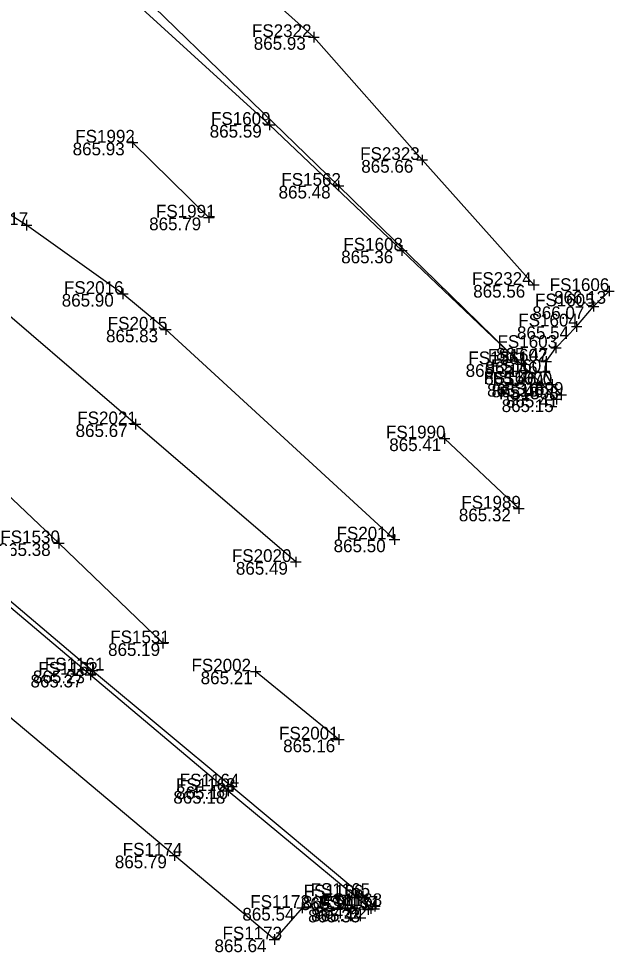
# Model space of a CAD drawing. Extents: x 1479420 to 1479833, y 379731 to 380103.
# Drawn here: x 1479768.1 to 1479824.3, y 379731.9 to 379820.1 of the extents above; entities that cross this region are included whole.
import ezdxf

# ---------------------------------------------------------------- set-up
doc = ezdxf.new("R2010")
doc.units = 0
for name, color, linetype in [('PM_X_CL_Double_Solid', 7, 'Continuous'), ('PM_X_Lane_Line', 7, 'Continuous'), ('PV_X_Curb', 7, 'Continuous'), ('PV_X_Walk', 7, 'Continuous'), ('SV_X_Shot_Marker', 7, 'Continuous'), ('SV_X_Text_Elevation', 7, 'Continuous'), ('SV_X_Text_Name', 7, 'Continuous'), ('UT_X_Gas', 7, 'Continuous'), ('UT_X_Water', 7, 'Continuous')]:
    doc.layers.add(name, color=color, linetype=linetype)

msp = doc.modelspace()

# ---------------------------------------------------------------- linework, layer by layer
at = {"layer": 'PM_X_CL_Double_Solid'}
for points in [[(1479794.219, 379768.772), (1479779.093, 379781.771), (1479763.159, 379795.427), (1479746.619, 379810.624), (1479732.239, 379823.873), (1479714.719, 379840.653), (1479700.713, 379853.615), (1479677.934, 379875.066)], [(1479803.529, 379770.896), (1479781.948, 379790.708), (1479777.891, 379794.074), (1479768.812, 379800.571), (1479752.353, 379810.888), (1479732.762, 379823.628)]]:
    msp.add_lwpolyline(points, dxfattribs=at)
at = {"layer": 'PM_X_Lane_Line'}
for p, q in [((1479786.008, 379801.285), (1479778.818, 379808.36)), ((1479815.248, 379773.81), (1479808.249, 379780.438)), ((1479798.265, 379752.014), (1479790.425, 379758.434))]:
    msp.add_line(p, q, dxfattribs=at)
at = {"layer": 'PV_X_Curb'}
for points in [[(1479818.811, 379784.125), (1479817.439, 379785.583), (1479804.233, 379798.167), (1479791.741, 379810.033), (1479778.638, 379821.983), (1479775.464, 379824.819), (1479758.378, 379840.845), (1479740.8, 379857.042), (1479740.592, 379857.626), (1479737.808, 379860.038), (1479735.87, 379861.852), (1479733.787, 379863.763), (1479718.701, 379877.898), (1479705.478, 379890.334), (1479700.95, 379894.575), (1479699.048, 379897.264), (1479697.778, 379899.5), (1479696.445, 379902.732), (1479695.776, 379905.397), (1479695.475, 379907.419), (1479695.142, 379911.53), (1479695.083, 379915.321)], [(1479667.239, 379857.122), (1479681.024, 379844.208), (1479695.135, 379830.978), (1479709.331, 379817.708), (1479723.729, 379804.193), (1479729.719, 379798.6), (1479748.963, 379780.548), (1479759.065, 379771.485), (1479760.185, 379770.473), (1479774.837, 379758.13), (1479787.835, 379747.16), (1479799.962, 379737.109), (1479801.3, 379736.045)], [(1479667.529, 379857.521), (1479681.356, 379844.557), (1479695.384, 379831.416), (1479709.512, 379818.131), (1479724.003, 379804.728), (1479730.662, 379798.272), (1479750.68, 379779.69), (1479759.253, 379771.893), (1479760.555, 379770.78), (1479775.03, 379758.526), (1479788.183, 379747.585), (1479800.537, 379737.251), (1479801.677, 379736.292)], [(1479819.259, 379784.557), (1479818.41, 379785.516), (1479817.726, 379786.711), (1479817.841, 379787.691), (1479818.764, 379788.982), (1479820.716, 379791.008), (1479822.306, 379792.903), (1479823.77, 379794.351)]]:
    msp.add_lwpolyline(points, dxfattribs=at)
at = {"layer": 'PV_X_Walk'}
msp.add_lwpolyline([(1479801.031, 379735.954), (1479794.804, 379736.123), (1479792.191, 379733.142), (1479782.769, 379741.06), (1479767.055, 379754.294), (1479759.061, 379761.026), (1479757.309, 379762.481), (1479754.256, 379765.105), (1479744.261, 379773.561), (1479732.859, 379783.688), (1479719.35, 379796.384), (1479703.027, 379811.462), (1479682.443, 379830.686), (1479657.296, 379854.468)], dxfattribs=at)
at = {"layer": 'SV_X_Shot_Marker'}
for p, q in [((1479795.406, 379818.324), (1479796.406, 379818.324)), ((1479795.906, 379818.824), (1479795.906, 379817.824)), ((1479795.906, 379818.324), (1479795.906, 379818.324)), ((1479791.741, 379810.533), (1479791.741, 379809.533)), ((1479791.241, 379810.033), (1479792.241, 379810.033)), ((1479791.741, 379810.033), (1479791.741, 379810.033)), ((1479778.818, 379808.86), (1479778.818, 379807.86)), ((1479778.318, 379808.36), (1479779.318, 379808.36)), ((1479778.818, 379808.36), (1479778.818, 379808.36)), ((1479805.628, 379806.719), (1479806.628, 379806.719)), ((1479806.128, 379807.219), (1479806.128, 379806.219)), ((1479806.128, 379806.719), (1479806.128, 379806.719)), ((1479797.748, 379804.283), (1479798.748, 379804.283)), ((1479798.248, 379804.783), (1479798.248, 379803.783)), ((1479798.248, 379804.283), (1479798.248, 379804.283)), ((1479786.008, 379801.785), (1479786.008, 379800.785)), ((1479768.312, 379800.571), (1479769.312, 379800.571)), ((1479768.812, 379801.071), (1479768.812, 379800.071)), ((1479768.812, 379800.571), (1479768.812, 379800.571)), ((1479785.508, 379801.285), (1479786.508, 379801.285)), ((1479786.008, 379801.285), (1479786.008, 379801.285)), ((1479803.733, 379798.167), (1479804.733, 379798.167)), ((1479804.233, 379798.667), (1479804.233, 379797.667)), ((1479804.233, 379798.167), (1479804.233, 379798.167)), ((1479816.671, 379795.427), (1479816.671, 379794.427)), ((1479777.891, 379794.574), (1479777.891, 379793.574)), ((1479816.171, 379794.927), (1479817.171, 379794.927)), ((1479816.671, 379794.927), (1479816.671, 379794.927)), ((1479823.27, 379794.351), (1479824.27, 379794.351)), ((1479823.77, 379794.851), (1479823.77, 379793.851)), ((1479823.77, 379794.351), (1479823.77, 379794.351)), ((1479777.391, 379794.074), (1479778.391, 379794.074)), ((1479777.891, 379794.074), (1479777.891, 379794.074)), ((1479821.806, 379792.903), (1479822.806, 379792.903)), ((1479822.306, 379793.403), (1479822.306, 379792.403)), ((1479822.306, 379792.903), (1479822.306, 379792.903)), ((1479781.948, 379791.208), (1479781.948, 379790.208)), ((1479820.216, 379791.008), (1479821.216, 379791.008)), ((1479820.716, 379791.508), (1479820.716, 379790.508)), ((1479820.716, 379791.008), (1479820.716, 379791.008)), ((1479781.448, 379790.708), (1479782.448, 379790.708)), ((1479781.948, 379790.708), (1479781.948, 379790.708)), ((1479818.764, 379789.482), (1479818.764, 379788.482)), ((1479817.841, 379788.191), (1479817.841, 379787.191)), ((1479818.264, 379788.982), (1479819.264, 379788.982)), ((1479818.764, 379788.982), (1479818.764, 379788.982)), ((1479814.968, 379787.444), (1479815.968, 379787.444)), ((1479815.468, 379787.944), (1479815.468, 379786.944)), ((1479815.468, 379787.444), (1479815.468, 379787.444)), ((1479817.341, 379787.691), (1479818.341, 379787.691)), ((1479817.841, 379787.691), (1479817.841, 379787.691)), ((1479817.226, 379786.711), (1479818.226, 379786.711)), ((1479817.726, 379787.211), (1479817.726, 379786.211)), ((1479817.726, 379786.711), (1479817.726, 379786.711)), ((1479816.939, 379785.583), (1479817.939, 379785.583)), ((1479817.439, 379786.083), (1479817.439, 379785.083)), ((1479817.439, 379785.583), (1479817.439, 379785.583)), ((1479817.91, 379785.516), (1479818.91, 379785.516)), ((1479818.41, 379786.016), (1479818.41, 379785.016)), ((1479818.41, 379785.516), (1479818.41, 379785.516)), ((1479818.811, 379784.625), (1479818.811, 379783.625)), ((1479819.259, 379785.057), (1479819.259, 379784.057)), ((1479818.311, 379784.125), (1479819.311, 379784.125)), ((1479818.759, 379784.557), (1479819.759, 379784.557)), ((1479818.811, 379784.125), (1479818.811, 379784.125)), ((1479819.259, 379784.557), (1479819.259, 379784.557)), ((1479779.093, 379782.271), (1479779.093, 379781.271)), ((1479778.593, 379781.771), (1479779.593, 379781.771)), ((1479779.093, 379781.771), (1479779.093, 379781.771)), ((1479807.749, 379780.438), (1479808.749, 379780.438)), ((1479808.249, 379780.938), (1479808.249, 379779.938)), ((1479808.249, 379780.438), (1479808.249, 379780.438)), ((1479815.248, 379774.31), (1479815.248, 379773.31)), ((1479814.748, 379773.81), (1479815.748, 379773.81)), ((1479815.248, 379773.81), (1479815.248, 379773.81)), ((1479803.529, 379771.396), (1479803.529, 379770.396)), ((1479771.342, 379770.542), (1479772.342, 379770.542)), ((1479771.842, 379771.042), (1479771.842, 379770.042)), ((1479771.842, 379770.542), (1479771.842, 379770.542)), ((1479803.029, 379770.896), (1479804.029, 379770.896)), ((1479803.529, 379770.896), (1479803.529, 379770.896)), ((1479793.719, 379768.772), (1479794.719, 379768.772)), ((1479794.219, 379769.272), (1479794.219, 379768.272)), ((1479794.219, 379768.772), (1479794.219, 379768.772)), ((1479781.178, 379761.101), (1479782.178, 379761.101)), ((1479781.678, 379761.601), (1479781.678, 379760.601)), ((1479781.678, 379761.101), (1479781.678, 379761.101)), ((1479774.53, 379758.526), (1479775.53, 379758.526)), ((1479774.837, 379758.63), (1479774.837, 379757.63)), ((1479775.03, 379759.026), (1479775.03, 379758.026)), ((1479775.03, 379758.526), (1479775.03, 379758.526)), ((1479789.925, 379758.434), (1479790.925, 379758.434)), ((1479790.425, 379758.934), (1479790.425, 379757.934)), ((1479790.425, 379758.434), (1479790.425, 379758.434)), ((1479774.337, 379758.13), (1479775.337, 379758.13)), ((1479774.837, 379758.13), (1479774.837, 379758.13)), ((1479797.765, 379752.014), (1479798.765, 379752.014)), ((1479798.265, 379752.514), (1479798.265, 379751.514)), ((1479798.265, 379752.014), (1479798.265, 379752.014)), ((1479787.683, 379747.585), (1479788.683, 379747.585)), ((1479787.835, 379747.66), (1479787.835, 379746.66)), ((1479788.183, 379748.085), (1479788.183, 379747.085)), ((1479788.183, 379747.585), (1479788.183, 379747.585)), ((1479787.335, 379747.16), (1479788.335, 379747.16)), ((1479787.835, 379747.16), (1479787.835, 379747.16)), ((1479782.769, 379741.56), (1479782.769, 379740.56)), ((1479782.269, 379741.06), (1479783.269, 379741.06)), ((1479782.769, 379741.06), (1479782.769, 379741.06)), ((1479799.462, 379737.109), (1479800.462, 379737.109)), ((1479799.962, 379737.609), (1479799.962, 379736.609)), ((1479799.962, 379737.109), (1479799.962, 379737.109)), ((1479800.037, 379737.251), (1479801.037, 379737.251)), ((1479800.537, 379737.751), (1479800.537, 379736.751)), ((1479800.537, 379737.251), (1479800.537, 379737.251)), ((1479794.804, 379736.623), (1479794.804, 379735.623)), ((1479801.031, 379736.454), (1479801.031, 379735.454)), ((1479801.177, 379736.292), (1479802.177, 379736.292)), ((1479801.3, 379736.545), (1479801.3, 379735.545)), ((1479801.677, 379736.792), (1479801.677, 379735.792)), ((1479801.677, 379736.292), (1479801.677, 379736.292)), ((1479794.304, 379736.123), (1479795.304, 379736.123)), ((1479794.804, 379736.123), (1479794.804, 379736.123)), ((1479800.531, 379735.954), (1479801.531, 379735.954)), ((1479800.8, 379736.045), (1479801.8, 379736.045)), ((1479801.031, 379735.954), (1479801.031, 379735.954)), ((1479801.3, 379736.045), (1479801.3, 379736.045)), ((1479792.191, 379733.642), (1479792.191, 379732.642)), ((1479791.691, 379733.142), (1479792.691, 379733.142)), ((1479792.191, 379733.142), (1479792.191, 379733.142))]:
    msp.add_line(p, q, dxfattribs=at)
at = {"layer": 'UT_X_Gas'}
msp.add_lwpolyline([(1479667.444, 379946.572), (1479666.862, 379942.802), (1479667.538, 379940.507), (1479675.403, 379934.504), (1479682.743, 379926.326), (1479692.421, 379916.824), (1479702.659, 379906.694), (1479713.881, 379895.567), (1479724.225, 379885.781), (1479733.117, 379877.795), (1479742.697, 379869.326), (1479754.816, 379857.131), (1479762.869, 379849.318), (1479772.436, 379840.641), (1479780.346, 379832.715), (1479784.901, 379828.191), (1479795.906, 379818.324), (1479806.128, 379806.719), (1479816.671, 379794.927)], dxfattribs=at)
at = {"layer": 'UT_X_Water'}
for points in [[(1479473.217, 380054.881), (1479498.741, 380029.974), (1479514.505, 380014.086), (1479533.448, 379996.735), (1479556.003, 379974.319), (1479574.861, 379956.271), (1479584.403, 379947.432), (1479599.597, 379932.819), (1479630.106, 379903.783), (1479644.769, 379889.722), (1479654.209, 379882.356), (1479664.266, 379872.629), (1479692.509, 379845.847), (1479712.672, 379826.686), (1479730.739, 379809.85), (1479753.15, 379788.309), (1479771.842, 379770.542), (1479781.678, 379761.101)], [(1479682.752, 379913.809), (1479688.353, 379908.314), (1479695.924, 379900.161), (1479705.441, 379891.596), (1479719.261, 379878.171), (1479726.79, 379870.913), (1479729.608, 379870.544), (1479735.551, 379869.684), (1479739.947, 379866.49), (1479744.65, 379861.847), (1479745.833, 379856.023), (1479753.929, 379847.124), (1479764.701, 379835.97), (1479779.815, 379822.167), (1479798.248, 379804.283), (1479815.468, 379787.444)]]:
    msp.add_lwpolyline(points, dxfattribs=at)

# ---------------------------------------------------------------- texts
at = {"layer": 'SV_X_Text_Elevation'}
for s, p in [('865.93', (1479790.247, 379817.124)), ('865.59', (1479786.091, 379808.833)), ('865.93', (1479773.159, 379807.16)), ('865.66', (1479800.393, 379805.519)), ('865.48', (1479792.589, 379803.083)), ('865.79', (1479780.377, 379800.085)), ('865.36', (1479798.498, 379796.967)), ('865.56', (1479810.955, 379793.727)), ('866.13', (1479818.584, 379793.151)), ('865.90', (1479772.128, 379792.874)), ('866.07', (1479816.533, 379791.703)), ('865.54', (1479815.085, 379789.808)), ('865.83', (1479776.307, 379789.508)), ('865.47', (1479813.114, 379787.782)), ('865.31', (1479810.242, 379786.244)), ('865.46', (1479812.116, 379786.491)), ('865.46', (1479812.001, 379785.511)), ('865.19', (1479812.262, 379784.383)), ('865.46', (1479812.685, 379784.316)), ('865.15', (1479813.643, 379782.925)), ('865.41', (1479814.043, 379783.357)), ('865.67', (1479773.434, 379780.571)), ('865.41', (1479803.033, 379779.238)), ('865.32', (1479809.598, 379772.61)), ('865.38', (1479766.173, 379769.342)), ('865.50', (1479797.784, 379769.696)), ('865.49', (1479788.56, 379767.572)), ('865.19', (1479776.501, 379759.901)), ('865.23', (1479769.408, 379757.326)), ('865.21', (1479785.237, 379757.234)), ('865.37', (1479769.178, 379756.93)), ('865.16', (1479793.022, 379750.814)), ('865.10', (1479782.911, 379746.385)), ('865.18', (1479782.658, 379745.96)), ('865.79', (1479777.138, 379739.86)), ('865.10', (1479794.69, 379735.909)), ('864.94', (1479794.878, 379736.051)), ('865.54', (1479789.173, 379734.923)), ('864.92', (1479796.018, 379735.092)), ('865.33', (1479795.372, 379734.754)), ('865.44', (1479795.659, 379734.845)), ('865.64', (1479786.541, 379731.942))]:
    msp.add_text(s, height=1.2, dxfattribs=at).set_placement(p)
at = {"layer": 'SV_X_Text_Name'}
for s, p in [('FS2322', (1479790.077, 379818.324)), ('FS1609', (1479786.214, 379810.033)), ('FS1992', (1479773.405, 379808.36)), ('FS2323', (1479800.289, 379806.719)), ('FS1562', (1479792.854, 379804.283)), ('FS1991', (1479781.019, 379801.285)), ('FS2017', (1479763.333, 379800.571)), ('FS1608', (1479798.706, 379798.167)), ('FS2324', (1479810.842, 379794.927)), ('FS2016', (1479772.336, 379794.074)), ('FS1606', (1479818.177, 379794.351)), ('FS1605', (1479816.789, 379792.903)), ('FS2015', (1479776.469, 379790.708)), ('FS1604', (1479815.208, 379791.008)), ('FS1603', (1479813.247, 379788.982)), ('FS1561', (1479810.498, 379787.444)), ('FS1602', (1479812.333, 379787.691)), ('FS1601', (1479812.643, 379786.711)), ('FS1607', (1479811.922, 379785.583)), ('FS1600', (1479812.789, 379785.516)), ('FS1599', (1479813.846, 379784.557)), ('FS1598', (1479813.398, 379784.125)), ('FS2021', (1479773.593, 379781.771)), ('FS1990', (1479802.722, 379780.438)), ('FS1989', (1479809.835, 379773.81)), ('FS1530', (1479766.334, 379770.542)), ('FS2014', (1479798.059, 379770.896)), ('FS2020', (1479788.182, 379768.772)), ('FS1531', (1479776.708, 379761.101)), ('FS1162', (1479769.916, 379758.13)), ('FS1161', (1479770.533, 379758.526)), ('FS2002', (1479784.369, 379758.434)), ('FS2001', (1479792.633, 379752.014)), ('FS1164', (1479783.262, 379747.585)), ('FS1163', (1479782.904, 379747.16)), ('FS1174', (1479777.886, 379741.06)), ('FS1166', (1479794.956, 379737.109)), ('FS1165', (1479795.606, 379737.251)), ('FS1172', (1479789.921, 379736.123)), ('FS1167', (1479796.369, 379736.045)), ('FS1171', (1479796.572, 379735.954)), ('FS1168', (1479796.737, 379736.292)), ('FS1173', (1479787.298, 379733.142))]:
    msp.add_text(s, height=1.2, dxfattribs=at).set_placement(p)

doc.saveas('drawing.dxf')
